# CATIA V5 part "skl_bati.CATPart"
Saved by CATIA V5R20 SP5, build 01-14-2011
Part number: skl_bati
Publications: "Point.1", "Point.2", "Plan_ref", "Point.3", "Axe_pivot_bati_exentrique", "Axe_pivot_bati_bielle_3", "Axe_glissiere_bati_coulisseau", "Plan_glissiere_bati_coulisseau"
Bounding box of the stored display mesh (mm): x -10 to 10, y -90 to 140, z 10 to 100
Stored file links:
  U:\2A\IAO\ThinkMotion\skl_bati.CATPart
  U:\2A\IAO\ThinkMotion\skl.CATProduct
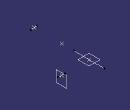
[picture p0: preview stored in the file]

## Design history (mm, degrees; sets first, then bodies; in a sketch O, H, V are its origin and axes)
Set1
  Point1: linked copy from another document
  Point2: linked copy from another document
  Plane1 "Plan_ref": linked copy from another document
  Point3: linked copy from another document
  Point4: linked copy from another document
Set2
  Line1 "Axe_pivot_bati_exentrique": type Normal, RefPoint Point1, RefSkin yz-plane, Start -10, End 10
  Line2 "Axe_pivot_bati_bielle_3": type PtDir, RefPoint Point4, Direction Plane1, Start -10, End 10
  Line3 "Axe_glissiere_bati_coulisseau": type PtDir, RefPoint Point3, Direction zx-plane, Start -50, End 50
  Plane2 "Plan_glissiere_bati_coulisseau": type OffsetPt, RefPlane xy-plane, RefPoint Point3
Body1 (main body)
